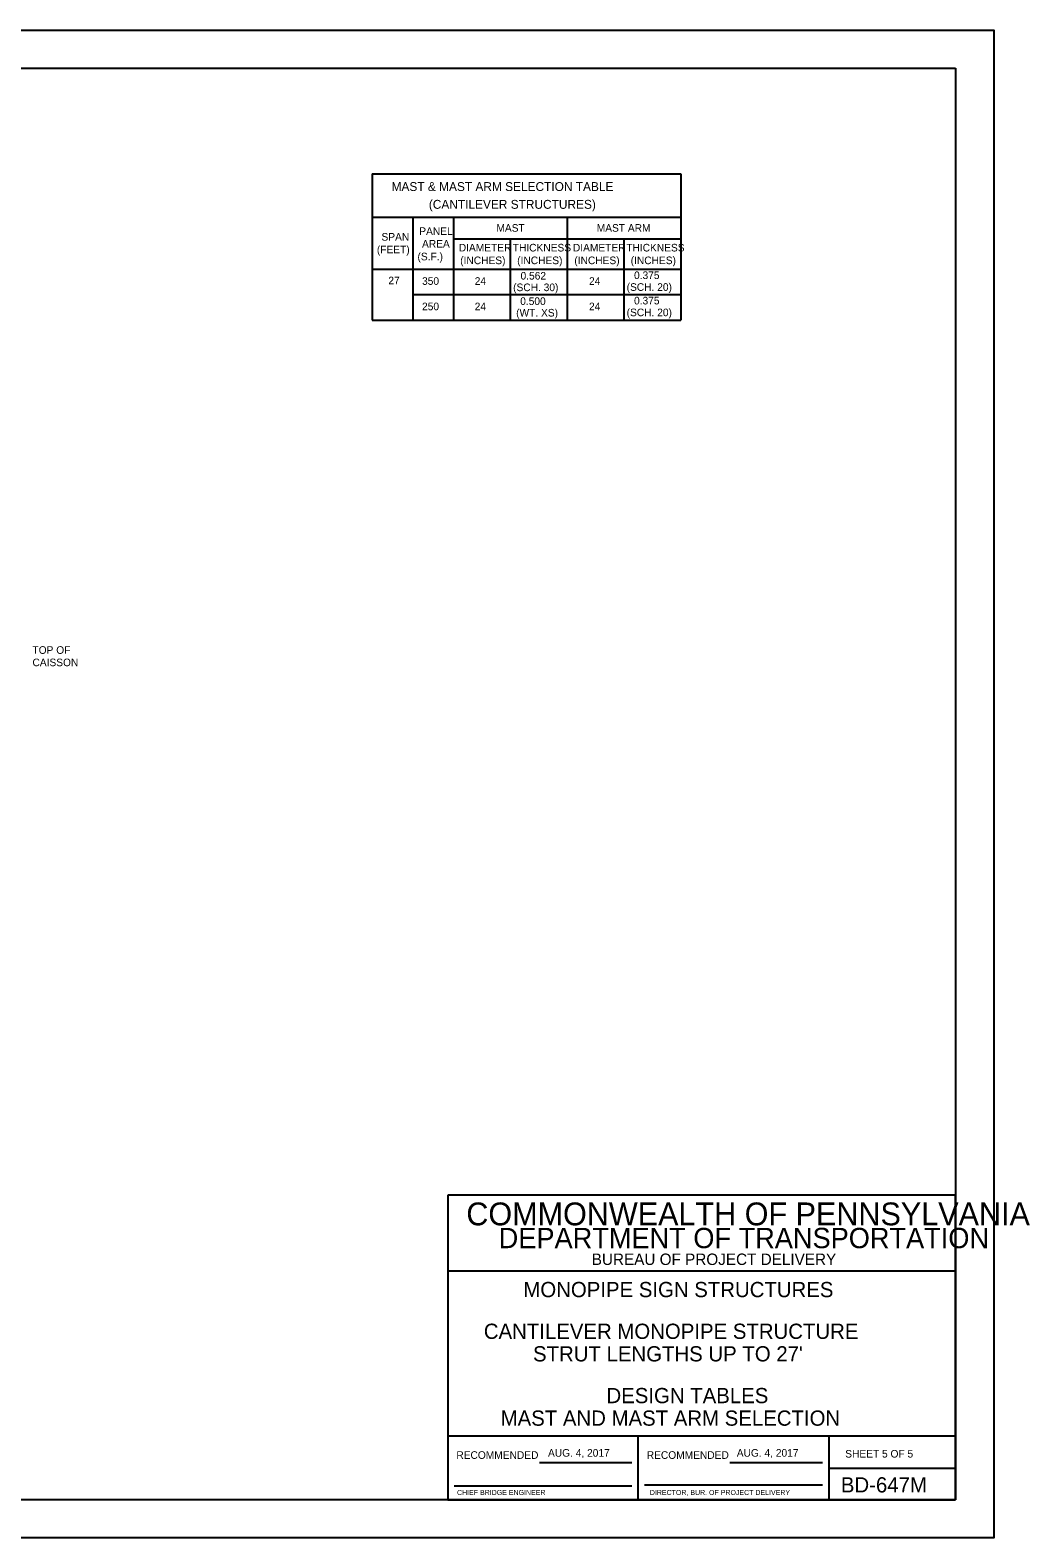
# Model space of a CAD drawing. Extents: x 640117 to 642655, y 297247 to 298435.
# Drawn here: x 642261 to 642655, y 297841 to 298435 of the extents above; entities that cross this region are included whole.
import ezdxf

# ---------------------------------------------------------------- set-up
doc = ezdxf.new("R2010")
doc.units = 0
for name, color, linetype in [('1', 7, 'Continuous'), ('10', 7, 'Continuous'), ('2', 7, 'Continuous'), ('3', 7, 'Continuous'), ('52', 7, 'Continuous'), ('53', 7, 'Continuous'), ('PLT-BNDY', 7, 'Continuous')]:
    doc.layers.add(name, color=color, linetype=linetype)

msp = doc.modelspace()

# ---------------------------------------------------------------- linework, layer by layer
at = {"layer": '1'}
for p, q in [((642500.46, 297856.46), (642500.46, 297881.46)), ((642461.54, 297871.17), (642497.96, 297871.17)), ((642536.54, 297871.17), (642572.96, 297871.17)), ((642427.96, 297861.96), (642497.96, 297861.96)), ((642502.96, 297862.33), (642572.96, 297862.33))]:
    msp.add_line(p, q, dxfattribs=at)
at = {"layer": '2'}
for p, q in [((641839.46, 298420.46), (642625.46, 298420.46)), ((642625.46, 298420.46), (642625.46, 297856.46)), ((642625.46, 297976.46), (642425.46, 297976.46)), ((642425.46, 297976.46), (642425.46, 297856.46)), ((642625.46, 297856.46), (642625.46, 297976.46)), ((642625.46, 297946.46), (642425.46, 297946.46)), ((642625.46, 297881.46), (642425.46, 297881.46)), ((642575.46, 297881.46), (642575.46, 297856.46)), ((642575.46, 297868.96), (642625.46, 297868.96)), ((642625.46, 297856.46), (641839.46, 297856.46)), ((642425.46, 297856.46), (642625.46, 297856.46))]:
    msp.add_line(p, q, dxfattribs=at)
at = {"layer": '3'}
for p, q in [((642395.61, 298378.86), (642395.61, 298321.26)), ((642395.61, 298378.86), (642517.21, 298378.86)), ((642517.21, 298378.86), (642517.21, 298321.26)), ((642395.61, 298361.8), (642517.21, 298361.8)), ((642411.61, 298361.8), (642411.61, 298321.26)), ((642427.61, 298361.8), (642427.61, 298321.26)), ((642472.41, 298361.8), (642472.41, 298321.26)), ((642427.61, 298353.26), (642517.21, 298353.26)), ((642450.01, 298353.26), (642450.01, 298321.26)), ((642494.81, 298353.26), (642494.81, 298321.26)), ((642395.61, 298341.26), (642517.21, 298341.26)), ((642411.61, 298331.26), (642517.21, 298331.26)), ((642395.61, 298321.26), (642517.21, 298321.26))]:
    msp.add_line(p, q, dxfattribs=at)
at = {"layer": 'PLT-BNDY'}
msp.add_lwpolyline([(641799.46, 298435.46), (642640.46, 298435.46), (642640.46, 297841.46), (641799.46, 297841.46)], close=True, dxfattribs=at)

# ---------------------------------------------------------------- texts
at = {"layer": '1'}
for s, height, p in [('RECOMMENDED', 3, (642428.79, 297872.58)), ('RECOMMENDED', 3, (642503.79, 297872.58)), ('CHIEF BRIDGE ENGINEER', 2.0002, (642429.05, 297858.33)), ('DIRECTOR, BUR. OF PROJECT DELIVERY', 2.0002, (642505, 297858.33))]:
    msp.add_text(s, height=height, dxfattribs=at).set_placement(p)
at = {"layer": '10'}
for s, p in [('MONOPIPE SIGN STRUCTURES', (642455.18, 297936.28)), ('CANTILEVER MONOPIPE STRUCTURE', (642439.61, 297919.84)), ("STRUT LENGTHS UP TO 27'", (642458.98, 297910.96)), ('DESIGN TABLES', (642487.92, 297894.51)), ('MAST AND MAST ARM SELECTION', (642446.23, 297885.63)), ('BD-647M', (642580.25, 297859.33))]:
    msp.add_text(s, height=6, dxfattribs=at).set_placement(p)
at = {"layer": '2'}
for s, height, p in [('COMMONWEALTH OF PENNSYLVANIA', 9, (642432.71, 297964.58)), ('DEPARTMENT OF TRANSPORTATION', 8.0002, (642445.46, 297955.58)), ('BUREAU OF PROJECT DELIVERY', 4.5, (642482.12, 297948.96)), ('SHEET 5 OF 5', 3, (642581.97, 297873.08))]:
    msp.add_text(s, height=height, dxfattribs=at).set_placement(p)
at = {"layer": '52'}
for p in [(642464.89, 297873.43), (642539.25, 297873.43)]:
    msp.add_text('AUG. 4, 2017', height=3, dxfattribs=at).set_placement(p)
at = {"layer": '53'}
for s, height, p in [('MAST & MAST ARM SELECTION TABLE', 3.5, (642403.27, 298372.08)), ('(CANTILEVER STRUCTURES)', 3.5, (642417.95, 298365.08)), ('SPAN', 3, (642399.3, 298352.53)), ('PANEL', 3, (642414.18, 298354.77)), ('MAST', 3, (642444.57, 298356.03)), ('MAST ARM', 3, (642484.09, 298356.03)), ('(FEET)', 3, (642397.48, 298347.53)), ('AREA', 3, (642415.27, 298349.77)), ('DIAMETER', 3, (642429.74, 298348.26)), ('THICKNESS', 3, (642451.01, 298348.26)), ('DIAMETER', 3, (642474.7, 298348.26)), ('THICKNESS', 3, (642495.72, 298348.26)), ('(S.F.)', 3, (642413.48, 298344.77)), ('(INCHES)', 3, (642430.3, 298343.26)), ('(INCHES)', 3, (642452.74, 298343.26)), ('(INCHES)', 3, (642475.26, 298343.26)), ('(INCHES)', 3, (642497.46, 298343.26)), ('27', 3, (642402, 298335.33)), ('350', 3, (642415.27, 298335.11)), ('24', 3, (642436.02, 298335.11)), ('0.562', 3, (642454.07, 298337.19)), ('24', 3, (642481.04, 298335.11)), ('0.375', 3, (642498.78, 298337.4)), ('(SCH. 30)', 3, (642451.15, 298332.63)), ('(SCH. 20)', 3, (642495.87, 298332.75)), ('250', 3, (642415.27, 298325.11)), ('24', 3, (642436.02, 298325.11)), ('(WT. XS)', 3, (642452.34, 298322.63)), ('0.500', 3, (642453.94, 298327.19)), ('24', 3, (642481.04, 298325.11)), ('(SCH. 20)', 3, (642495.87, 298322.75)), ('0.375', 3, (642498.78, 298327.4)), ('TOP OF', 3, (642261.81, 298189.74)), ('CAISSON', 3, (642261.81, 298184.86))]:
    msp.add_text(s, height=height, dxfattribs=at).set_placement(p)

doc.saveas('drawing.dxf')
